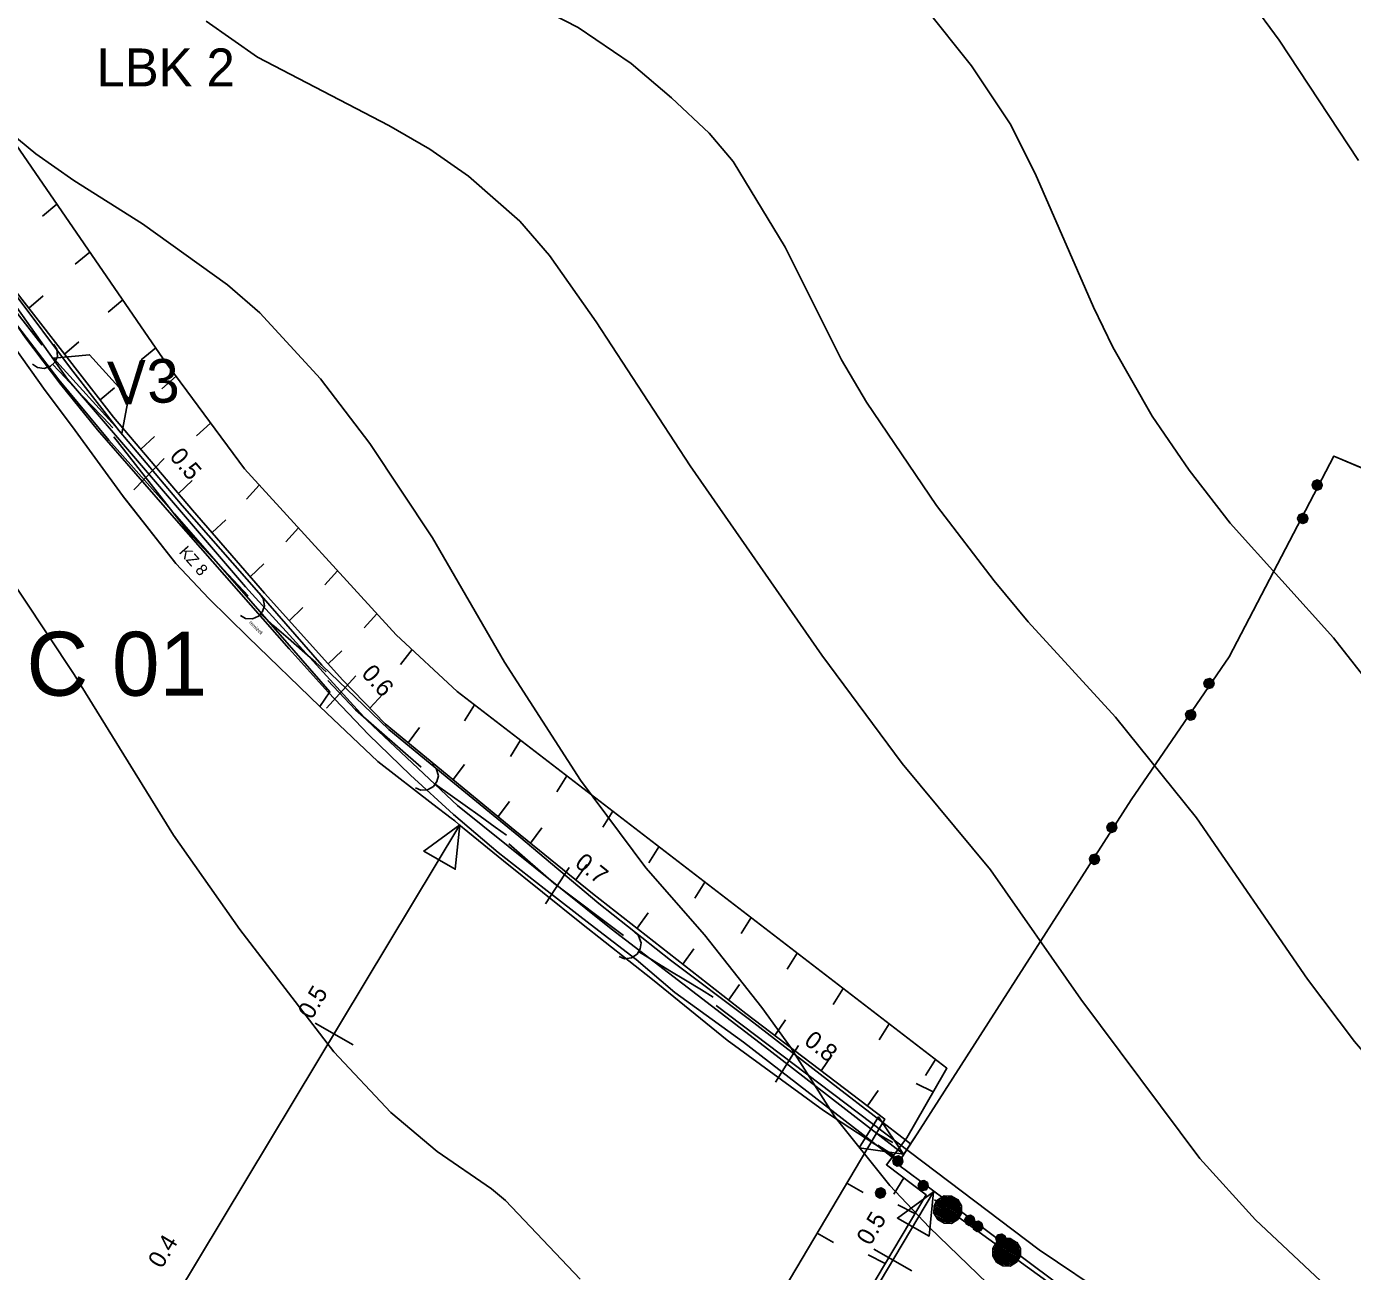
# Model space of a CAD drawing. Extents: x -645676 to -642474, y -1077513 to -1072613.
# Drawn here: x -643449.5 to -642993.3, y -1074361.2 to -1073932.9 of the extents above; entities that cross this region are included whole.
import ezdxf

# ---------------------------------------------------------------- set-up
doc = ezdxf.new("R2010")
doc.units = 0
for name, color, linetype in [('Kanalizace', 7, 'Continuous'), ('KRAJ_ZELEN_STAV', 7, 'Continuous'), ('Krajinn__zele____popis___stav', 7, 'Continuous'), ('KULTURY_STAV', 7, 'Continuous'), ('Lok_ln__biokoridor___navr_en_', 7, 'Continuous'), ('OBVOD_PU', 7, 'Continuous'), ('Odvodnen__cesty_pr_kopem___navr_en_', 7, 'Continuous'), ('PC_NAVRH', 7, 'Continuous'), ('PC_OBJ_POPIS_NAVRH', 7, 'Continuous'), ('PC_OBJEKTY_NAVRH', 7, 'Continuous'), ('PC_POPIS_NAVRH', 7, 'Continuous'), ('PC_STAN_NAVRH', 7, 'Continuous'), ('SPRAV_HR_STAV', 7, 'Continuous'), ('USES_BK_NAVRH', 7, 'Continuous'), ('USES_IP_NAVRH', 7, 'Continuous'), ('VRSTEVNICE', 7, 'Continuous')]:
    doc.layers.add(name, color=color, linetype=linetype)

# ---------------------------------------------------------------- blocks, each defined once
blk = doc.blocks.new('$944')
blk.add_line((0, 1.5), (0, -1.5))
blk = doc.blocks.new('$920')
for points in [[(0, 0), (-2.8, 1.25), (-2.8, -1.25), (0, 0)], [(-2.8, 1.25), (0, 0), (-2.8, -1.25), (-2.8, 1.25)]]:
    blk.add_lwpolyline(points)
blk = doc.blocks.new('$925')
for points in [[(-3.5, 0), (-2, 2), (2, 2), (3.5, 0), (-3.5, 0)], [(2, 2), (3.5, 0), (-3.5, 0), (-2, 2), (2, 2)]]:
    blk.add_lwpolyline(points)
blk = doc.blocks.new('2$1030')
blk.add_line((0, 0), (0, -0.5))
blk = doc.blocks.new('6$4100')
blk.add_lwpolyline([(0.19, 0.72), (0.53, 0.53), (0.72, 0.19), (0.72, -0.2), (0.53, -0.54), (0.19, -0.73), (-0.2, -0.73), (-0.54, -0.54), (-0.73, -0.2), (-0.75, 0.12), (-0.54, 0.52), (-0.2, 0.71), (0.19, 0.71), (0.2, 0.67), (-0.2, 0.67), (-0.36, 0.59), (0.36, 0.59), (0.44, 0.51), (-0.44, 0.51), (-0.52, 0.43), (0.52, 0.43), (0.6, 0.35), (-0.6, 0.35), (-0.6, 0.27), (0.6, 0.27), (0.68, 0.19), (-0.59, 0.19), (-0.68, 0.19), (-0.68, 0.11), (0.59, 0.11), (0.68, 0.11), (0.68, 0.03), (-0.59, 0.03), (-0.68, 0.03), (-0.68, -0.05), (0.59, -0.05), (0.68, -0.05), (0.68, -0.13), (-0.59, -0.13), (-0.68, -0.13), (-0.68, -0.21), (0.59, -0.21), (0.68, -0.21), (0.6, -0.29), (-0.6, -0.29), (-0.6, -0.37), (0.6, -0.37), (0.52, -0.45), (-0.52, -0.45), (-0.44, -0.53), (0.44, -0.53), (0.36, -0.61), (-0.36, -0.61), (-0.2, -0.69), (0.2, -0.69)])
blk = doc.blocks.new('6$2320')
for points in [[(-3.48, 1), (-3.08, 0.92), (-2.68, 0.6), (-2.53, 0.22), (-2.52, -0.2), (-2.72, -0.62), (-3.08, -0.92), (-3.48, -1)], [(-2.53, 0), (-1.26, 0), (0.01, 0), (1.28, 0), (2.55, 0), (3.5, 0)]]:
    blk.add_lwpolyline(points)
blk = doc.blocks.new('2$0620')
for points in [[(-1.07, 0.32), (-0.88, 0.13), (-0.88, -0.14), (-1.07, -0.33), (-1.34, -0.33), (-1.53, -0.14), (-1.53, 0.13), (-1.34, 0.32), (-1.07, 0.32), (-1.08, 0.28), (-1.32, 0.28), (-1.4, 0.2), (-1, 0.2), (-0.92, 0.12), (-1.48, 0.12), (-1.48, 0.04), (-0.92, 0.04), (-0.92, -0.04), (-1.48, -0.04), (-1.48, -0.12), (-0.92, -0.12), (-1, -0.2), (-1.4, -0.2), (-1.32, -0.28), (-1.08, -0.28)], [(1.43, 0.32), (1.62, 0.13), (1.62, -0.14), (1.43, -0.33), (1.16, -0.33), (0.97, -0.14), (0.97, 0.13), (1.16, 0.32), (1.43, 0.32), (1.4, 0.28), (1.16, 0.28), (1.08, 0.2), (1.48, 0.2), (1.56, 0.12), (1, 0.12), (1, 0.04), (1.56, 0.04), (1.56, -0.04), (1, -0.04), (1, -0.12), (1.56, -0.12), (1.48, -0.2), (1.08, -0.2), (1.16, -0.28), (1.4, -0.28)]]:
    blk.add_lwpolyline(points)

msp = doc.modelspace()

# ---------------------------------------------------------------- linework, layer by layer
at = {"layer": 'Kanalizace'}
for p, q in [((-643345.82, -1074157.9), (-643336.32, -1074168.01)), ((-643336.32, -1074168.01), (-643313.72, -1074187.73)), ((-643212.24, -1074269.74), (-643101.11, -1074353.68)), ((-643101.11, -1074353.68), (-643076.28, -1074370.51))]:
    msp.add_line(p, q, dxfattribs=at)
for points in [[(-643472.69, -1074004.03), (-643462.65, -1074018.91), (-643444.15, -1074042.53)], [(-643419.49, -1074074.02), (-643393.75, -1074106.88), (-643373.21, -1074128.74)], [(-643283.59, -1074214.03), (-643268.1, -1074227.55), (-643244.16, -1074245.64)]]:
    msp.add_lwpolyline(points, dxfattribs=at)
at = {"layer": 'KRAJ_ZELEN_STAV'}
msp.add_lwpolyline([(-643348.62, -1074166.81), (-643373.25, -1074143.01), (-643386.71, -1074129.73), (-643398.08, -1074117.62), (-643416.48, -1074094.22), (-643433.67, -1074070.61), (-643443.11, -1074058.09), (-643461.99, -1074031.6), (-643474.19, -1074013.98), (-643486.49, -1073995.49), (-643504.76, -1073968.7), (-643501.27, -1073967.33), (-643498.06, -1073968.92), (-643487.61, -1073984.81), (-643475.96, -1074003.57), (-643458.16, -1074028.49), (-643438.37, -1074054.46), (-643421.17, -1074075.19), (-643398.56, -1074100.56), (-643372.3, -1074130.6), (-643345.17, -1074161.79), (-643348.62, -1074166.81)], dxfattribs=at)
at = {"layer": 'KULTURY_STAV'}
for points in [[(-643453.68, -1074024.55), (-643434.38, -1074050.42), (-643417.59, -1074072.01), (-643395.98, -1074097.73), (-643369.61, -1074127.72), (-643347.92, -1074152.67), (-643324.84, -1074174.79), (-643303.55, -1074192.25), (-643280.18, -1074211.49), (-643252.59, -1074234.56), (-643227.96, -1074254.05), (-643200.74, -1074274.47), (-643170.39, -1074298.03), (-643145.4, -1074317.28), (-643143.15, -1074313.78), (-643145.39, -1074317.28), (-643149.86, -1074324.25), (-643149.09, -1074323.04), (-643169.25, -1074309.8), (-643175.33, -1074305.8), (-643208.41, -1074281.61), (-643234.13, -1074260.78), (-643258.52, -1074241.45), (-643285.41, -1074219.94), (-643297.69, -1074209.95), (-643300.74, -1074207.4), (-643302.19, -1074206.19), (-643303.43, -1074205.24), (-643309.68, -1074200.45), (-643328.66, -1074185.73), (-643346.28, -1074168.99), (-643348.62, -1074166.82), (-643373.25, -1074143.01), (-643386.71, -1074129.73), (-643398.09, -1074117.62), (-643416.2, -1074094.58), (-643416.48, -1074094.22), (-643433.67, -1074070.61), (-643443.11, -1074058.09), (-643461.99, -1074031.6)], [(-642952.44, -1074100.73), (-642999.74, -1074080.7), (-643035.82, -1074149.72), (-643069.51, -1074198.98), (-643143.15, -1074313.78), (-643145.4, -1074317.28), (-643170.39, -1074298.03), (-643200.74, -1074274.47), (-643227.96, -1074254.05), (-643252.59, -1074234.56), (-643280.18, -1074211.49), (-643303.55, -1074192.25), (-643324.84, -1074174.79), (-643347.92, -1074152.67), (-643369.61, -1074127.72), (-643395.98, -1074097.73), (-643417.59, -1074072.01), (-643434.38, -1074050.42), (-643453.68, -1074024.55)], [(-643461.99, -1074031.6), (-643443.11, -1074058.09), (-643433.67, -1074070.61), (-643416.48, -1074094.22), (-643416.2, -1074094.58), (-643398.09, -1074117.62), (-643386.71, -1074129.73), (-643373.25, -1074143.01), (-643348.62, -1074166.82), (-643346.28, -1074168.99), (-643328.66, -1074185.73), (-643309.68, -1074200.45), (-643303.43, -1074205.24), (-643302.19, -1074206.19), (-643300.74, -1074207.4), (-643297.69, -1074209.95), (-643285.41, -1074219.94), (-643258.52, -1074241.45), (-643234.13, -1074260.78), (-643208.41, -1074281.61), (-643175.33, -1074305.8), (-643169.25, -1074309.8), (-643149.09, -1074323.04), (-643149.86, -1074324.25), (-643133.84, -1074336.21), (-643131.09, -1074338.26), (-643090.44, -1074368.63)]]:
    msp.add_lwpolyline(points, dxfattribs=at)
at = {"layer": 'OBVOD_PU'}
msp.add_lwpolyline([(-642952.44, -1074100.73), (-642999.74, -1074080.7), (-643035.82, -1074149.72), (-643069.51, -1074198.98), (-643143.15, -1074313.78), (-643149.86, -1074324.25), (-643133.84, -1074336.21), (-643131.09, -1074338.26), (-643090.44, -1074368.63)], dxfattribs=at)
at = {"layer": 'Odvodnen__cesty_pr_kopem___navr_en_'}
msp.add_lwpolyline([(-643149.66, -1074323.43), (-643202.88, -1074282.33), (-643226.42, -1074265.26), (-643239.75, -1074253.89), (-643255.58, -1074241.67), (-643271.42, -1074229.45), (-643287.19, -1074217.01), (-643302.55, -1074204.03), (-643317.44, -1074190.51), (-643331.84, -1074176.47), (-643345.74, -1074161.94), (-643359.12, -1074146.97), (-643372.33, -1074131.95), (-643398.74, -1074101.91), (-643425.07, -1074071.7), (-643437.71, -1074056.06), (-643449.78, -1074039.97), (-643472.68, -1074007.1), (-643484.07, -1073990.66), (-643498.57, -1073971.2), (-643507.02, -1073957.96), (-643518.78, -1073941.84), (-643542.91, -1073910.01)], dxfattribs=at)
at = {"layer": 'PC_NAVRH'}
for points in [[(-643699.19, -1073681.85), (-643673.6, -1073712.41), (-643664.43, -1073728.78), (-643639.3, -1073773.55), (-643628.83, -1073790.6), (-643611.21, -1073816.03), (-643592.93, -1073839.85), (-643545.81, -1073900.9), (-643507.54, -1073952.15), (-643483.08, -1073986.87), (-643435.34, -1074054.23), (-643374.17, -1074125.66), (-643332.32, -1074171.6), (-643301.24, -1074200.87), (-643248.32, -1074243.3), (-643194.15, -1074284.9), (-643147.82, -1074320.78)], [(-643601.67, -1074707.74), (-643569.87, -1074655.21), (-643300.39, -1074207.59)], [(-643407.19, -1074786.84), (-643347.52, -1074686.8), (-643272.31, -1074560.44), (-643137.51, -1074333.74)]]:
    msp.add_lwpolyline(points, dxfattribs=at)
at = {"layer": 'SPRAV_HR_STAV'}
for p, q in [((-642999.74, -1074080.7), (-643035.82, -1074149.72)), ((-642952.44, -1074100.73), (-642999.74, -1074080.7)), ((-643035.82, -1074149.72), (-643069.51, -1074198.98)), ((-643069.51, -1074198.98), (-643143.15, -1074313.78)), ((-643143.15, -1074313.78), (-643149.86, -1074324.25)), ((-643149.86, -1074324.25), (-643133.84, -1074336.21)), ((-643133.84, -1074336.21), (-643131.09, -1074338.26)), ((-643131.09, -1074338.26), (-643090.44, -1074368.63))]:
    msp.add_line(p, q, dxfattribs=at)
at = {"layer": 'USES_BK_NAVRH'}
for points in [[(-643365.02, -1074664.02), (-643154.25, -1074308.76), (-643202.04, -1074272.42), (-643254.74, -1074231.15), (-643281.49, -1074209.44), (-643326.14, -1074172.74), (-643340.63, -1074157.75), (-643367.66, -1074127.85), (-643392.35, -1074099.24), (-643419.6, -1074067.32), (-643456.29, -1074020.07), (-643488.65, -1073967.87), (-643493.42, -1073961.92), (-643503.27, -1073950.91), (-643559.37, -1073878.23), (-643584.6, -1073844.72), (-643598.15, -1073826.35), (-643622.66, -1073794.97), (-643644.55, -1073756.98), (-643662.32, -1073721.99), (-643645.55, -1073647.06), (-643529.9, -1073432)], [(-643507.19, -1073442.54), (-643621.79, -1073655.66), (-643633.31, -1073710.01), (-643602.63, -1073774.11), (-643549.96, -1073850.87), (-643465.95, -1073954.88), (-643402.48, -1074047.21), (-643374.54, -1074085.13), (-643322.34, -1074142.15), (-643301.3, -1074161.69), (-643132.86, -1074291.27), (-643133.86, -1074292.82), (-643146.7, -1074315.23), (-643153.67, -1074324.49), (-643140.05, -1074334.77), (-643371.48, -1074723.77)]]:
    msp.add_lwpolyline(points, dxfattribs=at)
at = {"layer": 'USES_IP_NAVRH'}
msp.add_lwpolyline([(-643137.08, -1074336.55), (-643025.8, -1074417.19), (-642894.04, -1074500.47), (-642796.02, -1074571.74)], dxfattribs=at)
at = {"layer": 'VRSTEVNICE'}
for points in [[(-643259.03, -1074363.78), (-643284.67, -1074336.72), (-643289.51, -1074332.73), (-643308.17, -1074319.91), (-643324.12, -1074306.52), (-643343.77, -1074285.59), (-643376.1, -1074243.58), (-643398.89, -1074211.1), (-643433.07, -1074155.84), (-643478.08, -1074088.34), (-643513.4, -1074039.91), (-643533.34, -1074014.85), (-643551.14, -1073996.19), (-643567.8, -1073980.95), (-643581.33, -1073969.84), (-643605.12, -1073952.47), (-643634.74, -1073933.52), (-643662.51, -1073914.44), (-643680.74, -1073900.48), (-643697.97, -1073885.39), (-643702.82, -1073880.12), (-643710.65, -1073869.86), (-643715.06, -1073865.87), (-643722.47, -1073856.47)], [(-643340.18, -1073899.06), (-643332.66, -1073901.76), (-643282.53, -1073921.42), (-643259.74, -1073933.24), (-643241.51, -1073945.63), (-643227.56, -1073957.45), (-643214.6, -1073969.56), (-643206.34, -1073979.38), (-643188.53, -1074008.86), (-643169.16, -1074047.6), (-643160.48, -1074062.13), (-643136.41, -1074097.74), (-643116.61, -1074123.66), (-643104.93, -1074137.75), (-643074.88, -1074170.51), (-643046.97, -1074205.12), (-643008.8, -1074260.67), (-642992.7, -1074282.03), (-642974.76, -1074302.96), (-642937.87, -1074341.56), (-642918.65, -1074359.93), (-642874.35, -1074397.96), (-642851.28, -1074420.6), (-642800.28, -1074483.73)], [(-643118.89, -1074365.35), (-643138.97, -1074345.98), (-643152.5, -1074331.59), (-643171.44, -1074307.95), (-643186.68, -1074284.02), (-643196.51, -1074270.35), (-643216.31, -1074245.43), (-643236.39, -1074222.35), (-643258.89, -1074192.16), (-643285.09, -1074151.57), (-643309.88, -1074108.84), (-643331.38, -1074076.37), (-643348.33, -1074054.15), (-643369.27, -1074031.37), (-643380.37, -1074021.83), (-643409.57, -1074000.75), (-643433.21, -1073985.94), (-643446.32, -1073976.68), (-643495.45, -1073936.09), (-643507.84, -1073926.97)], [(-642978.6, -1074170.37), (-642999.83, -1074143.17), (-643035.43, -1074103.72), (-643049.53, -1074085.49), (-643062.3, -1074066.93), (-643075.74, -1074043.19), (-643082.43, -1074029.51), (-643102.51, -1073983.51), (-643111.06, -1073966.42), (-643124.44, -1073946.48), (-643140.39, -1073926.54)], [(-643028.59, -1073924.12), (-643018.62, -1073937.65), (-642991.28, -1073978.96)], [(-642998.69, -1074369.62), (-643026.74, -1074343.41), (-643045.83, -1074322.33), (-643086.84, -1074267.5), (-643117.89, -1074223.07), (-643148.23, -1074186.46), (-643175.86, -1074149.15), (-643221.15, -1074084.06), (-643253.48, -1074034.5), (-643269.57, -1074011.71), (-643279.83, -1073999.89), (-643297.49, -1073984.37), (-643310.73, -1073975.11), (-643324.83, -1073966.99), (-643369.98, -1073943.49), (-643387.64, -1073931.1)]]:
    msp.add_lwpolyline(points, dxfattribs=at)

# ---------------------------------------------------------------- block references
at = {"layer": 'Kanalizace', "xscale": 5}
for p, yscale, rotation in [((-643431.82, -1074058.27), 5, -46.54941200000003), ((-643359.51, -1074143.32), 4.999999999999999, -41.32529900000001), ((-643298.65, -1074200.88), 5, -35.54837500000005), ((-643228.2, -1074257.69), 5, -31.427048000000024)]:
    msp.add_blockref('6$2320', p, dxfattribs=dict(at, yscale=yscale, rotation=rotation))
at = {"layer": 'PC_OBJEKTY_NAVRH', "xscale": 5, "yscale": 5.000000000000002, "rotation": -47.76780800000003}
msp.add_blockref('$925', (-643428.49, -1074059.97), dxfattribs=at)
at = {"layer": 'PC_STAN_NAVRH'}
for name, p, xscale, yscale, rotation in [('$944', (-643407.4, -1074086.86), 5, 5, -44.00190099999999), ('$944', (-643341.23, -1074161.81), 5, 5, -42.21220899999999), ('$920', (-643300.39, -1074207.59), 4.999999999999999, 5.000000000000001, 59.98052899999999), ('$944', (-643266.86, -1074228.44), 5, 5, -33.123897), ('$944', (-643343.66, -1074279.46), 4.999999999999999, 5.000000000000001, 59.98052899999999), ('$944', (-643187.87, -1074289.76), 5, 5, -32.13288500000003), ('$920', (-643147.82, -1074320.78), 5, 5, -32.13288500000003), ('$920', (-643137.51, -1074333.74), 4.999999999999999, 5.000000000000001, 60.29532300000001), ('$944', (-643151.46, -1074357.2), 4.999999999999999, 5.000000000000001, 60.29532300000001)]:
    msp.add_blockref(name, p, dxfattribs=dict(at, xscale=xscale, yscale=yscale, rotation=rotation))
at = {"layer": 'SPRAV_HR_STAV'}
for p, xscale, yscale, rotation in [((-643007.85, -1074096.21), 5, 4.999999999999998, -113.367489), ((-643045.7, -1074164.16), 5, 5.000000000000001, -120.256539), ((-643078.96, -1074213.71), 4.999999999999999, 4.999999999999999, -118.536646), ((-643152.59, -1074328.51), 5, 4.999999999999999, -118.51249000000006), ((-643135.84, -1074334.72), 5, 5, -31.1019), ((-643119.81, -1074346.67), 5, 5, -31.060258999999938), ((-643117.07, -1074348.73), 5, 4.999999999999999, -31.122220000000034)]:
    msp.add_blockref('2$0620', p, dxfattribs=dict(at, xscale=xscale, yscale=yscale, rotation=rotation))
at = {"layer": 'USES_BK_NAVRH'}
for p, xscale, yscale, rotation in [((-643439.04, -1073994.03), 13.000000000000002, 12.999999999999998, -50.18227900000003), ((-643427.71, -1074010.51), 13.000000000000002, 12.999999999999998, -50.18227900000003), ((-643448.74, -1074029.8), 12.999999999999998, 13, 130.06137), ((-643416.38, -1074026.99), 13.000000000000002, 12.999999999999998, -50.18227900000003), ((-643436.47, -1074045.6), 12.999999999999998, 13, 130.06137), ((-643405.05, -1074043.47), 13.000000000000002, 12.999999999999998, -50.18227900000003), ((-643398.03, -1074053.25), 13, 13, -48.26455099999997), ((-643424.2, -1074061.39), 12.999999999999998, 13, 130.06137), ((-643386.17, -1074069.35), 13, 13, -48.26455099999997), ((-643410.21, -1074078.32), 13, 13, 132.756305), ((-643397.22, -1074093.54), 13, 13, 132.756305), ((-643369.48, -1074090.66), 13, 13.000000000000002, -42.076750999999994), ((-643385.63, -1074107.03), 13, 13, 133.080564), ((-643355.97, -1074105.41), 13, 13.000000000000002, -42.076750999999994), ((-643372.56, -1074122.18), 13, 13, 133.080564), ((-643342.47, -1074120.17), 13, 13.000000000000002, -42.076750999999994), ((-643359.08, -1074137.35), 13, 13, 134.42056), ((-643328.96, -1074134.92), 13, 13.000000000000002, -42.076750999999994), ((-643345.66, -1074152.19), 13, 13, 134.42056), ((-643316.85, -1074147.26), 13, 13.000000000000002, -37.34968700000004), ((-643331.35, -1074167.35), 13, 13, 136.37049200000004), ((-643295.36, -1074166.27), 13.000000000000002, 12.999999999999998, -31.94263799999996), ((-643318.18, -1074179.28), 13, 13, 143.036452), ((-643279.51, -1074178.46), 13.000000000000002, 12.999999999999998, -31.94263799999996), ((-643302.73, -1074191.98), 13, 13, 143.036452), ((-643263.65, -1074190.66), 13.000000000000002, 12.999999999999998, -31.94263799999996), ((-643287.28, -1074204.68), 13, 13, 143.036452), ((-643247.8, -1074202.85), 13.000000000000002, 12.999999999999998, -31.94263799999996), ((-643276.09, -1074213.82), 13, 12.999999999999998, 143.396084), ((-643231.95, -1074215.05), 13.000000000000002, 12.999999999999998, -31.94263799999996), ((-643260.56, -1074226.42), 13, 12.999999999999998, 143.396084), ((-643216.1, -1074227.24), 13.000000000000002, 12.999999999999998, -31.94263799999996), ((-643239.44, -1074243.13), 13.000000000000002, 13.000000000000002, 144.409098), ((-643200.24, -1074239.44), 13.000000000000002, 12.999999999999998, -31.94263799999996), ((-643223.69, -1074255.47), 13.000000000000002, 13.000000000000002, 144.409098), ((-643184.39, -1074251.63), 13.000000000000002, 12.999999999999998, -31.94263799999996), ((-643207.95, -1074267.8), 13.000000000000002, 13.000000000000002, 144.409098), ((-643168.54, -1074263.82), 13.000000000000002, 12.999999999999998, -31.94263799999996), ((-643192.06, -1074280.01), 12.999999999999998, 13, 145.240663), ((-643152.69, -1074276.02), 13.000000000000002, 12.999999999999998, -31.94263799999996), ((-643176.14, -1074292.12), 12.999999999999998, 13, 145.240663), ((-643136.84, -1074288.21), 13.000000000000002, 12.999999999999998, -31.94263799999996), ((-643137.59, -1074299.33), 13.000000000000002, 13, -115.61731499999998), ((-643160.22, -1074304.23), 12.999999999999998, 13, 145.240663), ((-643157.1, -1074313.56), 13, 12.999999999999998, 60.355427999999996), ((-643151.21, -1074321.22), 13, 13, -122.906483), ((-643147.68, -1074329.01), 13.000000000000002, 13, -31.411064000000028), ((-643167.3, -1074330.76), 13, 12.999999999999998, 60.355427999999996), ((-643143.89, -1074341.22), 13.000000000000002, 13, -116.57369100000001), ((-643177.5, -1074347.96), 13, 12.999999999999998, 60.355427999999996), ((-643154.11, -1074358.4), 13.000000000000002, 13, -116.57369100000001)]:
    msp.add_blockref('2$1030', p, dxfattribs=dict(at, xscale=xscale, yscale=yscale, rotation=rotation))
at = {"layer": 'USES_IP_NAVRH', "xscale": 6.5, "yscale": 6.5, "rotation": -30.272696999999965}
for p in [(-643132.51, -1074339.86), (-643112.26, -1074354.53)]:
    msp.add_blockref('6$4100', p, dxfattribs=at)

# ---------------------------------------------------------------- texts
at = {"layer": 'Krajinn__zele____popis___stav'}
for s, height, rotation, p in [('KZ 8', 4, 311.585, (-643397.23, -1074113.81)), ('remízek', 1.2, 315.023, (-643372.99, -1074138.08))]:
    msp.add_text(s, height=height, rotation=rotation, dxfattribs=at).set_placement(p)
at = {"layer": 'Lok_ln__biokoridor___navr_en_'}
msp.add_text('LBK 2', height=13.05, dxfattribs=at).set_placement((-643425.37, -1073953.53))
at = {"layer": 'PC_OBJ_POPIS_NAVRH'}
msp.add_text('V3', height=15, rotation=2.865, dxfattribs=at).set_placement((-643421.09, -1074063.25))
at = {"layer": 'PC_POPIS_NAVRH'}
msp.add_text('C 01', height=22, dxfattribs=at).set_placement((-643449.5, -1074163.12))
at = {"layer": 'PC_STAN_NAVRH'}
for s, rotation, p in [('0.5', 310.6, (-643400.57, -1074081)), ('0.6', 312.319, (-643334.58, -1074155.75)), ('0.7', 321.257, (-643261.23, -1074221.42)), ('0.5', 58.957, (-643351.37, -1074274.82)), ('0.8', 322.231, (-643182.36, -1074282.64)), ('0.5', 59.244, (-643159.2, -1074352.6)), ('0.4', 58.957, (-643402.95, -1074360.49))]:
    msp.add_text(s, height=6, rotation=rotation, dxfattribs=at).set_placement(p)

doc.saveas('drawing.dxf')
